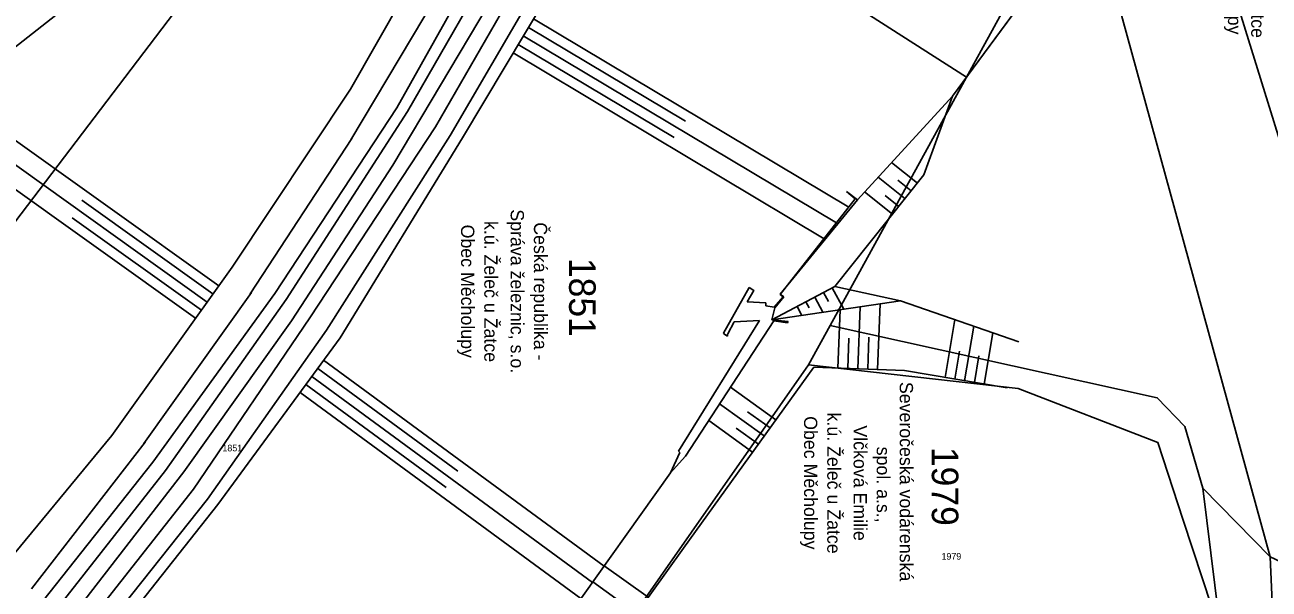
# Model space of a CAD drawing. Extents: x -801372 to -800991, y -1017235 to -1016862.
# Drawn here: x -801166.4 to -801072.7, y -1017121 to -1017078.6 of the extents above; entities that cross this region are included whole.
import ezdxf

# ---------------------------------------------------------------- set-up
doc = ezdxf.new("R2010")
doc.units = 0
for name, color, linetype in [('05a - kolej - svršek', 7, 'Continuous'), ('09 - stávající terén', 7, 'Continuous'), ('19 - katastr', 7, 'Continuous'), ('19b - katastr - hranice SŽDC', 7, 'Continuous'), ('19b - katastr popisy', 7, 'Continuous'), ('21g - SZDC', 7, 'Continuous'), ('26 - obvod_stavby', 7, 'Continuous'), ('27 - dočasné zábory', 7, 'Continuous'), ('Vrstva 1 - kolej', 7, 'Continuous'), ('Vrstva 25', 7, 'Continuous'), ('Vrstva 48 - svahy', 7, 'Continuous')]:
    doc.layers.add(name, color=color, linetype=linetype)

msp = doc.modelspace()

# ---------------------------------------------------------------- linework, layer by layer
for points in [[(-801079.49, -1017062.745), (-801060.39, -1017124.37)], [(-801086.965, -1017066.29), (-801072.61, -1017118.61)]]:
    msp.add_lwpolyline(points)
at = {"layer": '05a - kolej - svršek'}
for p, q in [((-801130.649, -1017070.959), (-801138.418, -1017084.801)), ((-801129.736, -1017071.4), (-801137.615, -1017085.081)), ((-801127.508, -1017072.406), (-801135.493, -1017086.234)), ((-801126.271, -1017073.005), (-801134.396, -1017086.885)), ((-801138.418, -1017084.801), (-801147.606, -1017098.787)), ((-801137.615, -1017085.081), (-801146.745, -1017099.245)), ((-801135.493, -1017086.234), (-801144.954, -1017100.614)), ((-801134.396, -1017086.885), (-801143.698, -1017101.543)), ((-801147.606, -1017098.787), (-801156.793, -1017111.486)), ((-801146.745, -1017099.245), (-801155.831, -1017112.103)), ((-801144.954, -1017100.614), (-801153.731, -1017113.517)), ((-801143.698, -1017101.543), (-801152.664, -1017114.263)), ((-801156.793, -1017111.486), (-801167.183, -1017124.594)), ((-801155.831, -1017112.103), (-801166.305, -1017125.438)), ((-801153.731, -1017113.517), (-801164.481, -1017127.151)), ((-801152.664, -1017114.263), (-801163.522, -1017127.928))]:
    msp.add_line(p, q, dxfattribs=at)
at = {"layer": '09 - stávající terén'}
for p, q in [((-801133.541, -1017068.702), (-801141.901, -1017083.399)), ((-801086.638, -1017070.523), (-801096.55, -1017083.938)), ((-801125.337, -1017073.453), (-801133.459, -1017087.061)), ((-801141.901, -1017083.399), (-801150.824, -1017096.807)), ((-801096.55, -1017083.938), (-801103.705, -1017091.722)), ((-801096.55, -1017083.938), (-801098.707, -1017089.859)), ((-801133.459, -1017087.061), (-801142.687, -1017102.127)), ((-801098.707, -1017089.859), (-801105.414, -1017098.252)), ((-801104.54, -1017091.105), (-801103.863, -1017091.657)), ((-801103.705, -1017091.722), (-801104.54, -1017091.105)), ((-801103.705, -1017091.722), (-801109.519, -1017098.831)), ((-801103.863, -1017091.657), (-801109.513, -1017098.855)), ((-801150.824, -1017096.807), (-801159.87, -1017109.48)), ((-801111.869, -1017098.328), (-801113.784, -1017101.768)), ((-801112.004, -1017099.415), (-801111.497, -1017098.559)), ((-801111.503, -1017098.564), (-801111.869, -1017098.328)), ((-801111.486, -1017098.551), (-801111.503, -1017098.564)), ((-801111.497, -1017098.559), (-801111.486, -1017098.551)), ((-801105.414, -1017098.252), (-801110.142, -1017100.764)), ((-801105.414, -1017098.252), (-801100.47, -1017099.329)), ((-801110.612, -1017099.486), (-801112.004, -1017099.415)), ((-801110.613, -1017099.715), (-801110.612, -1017099.486)), ((-801109.972, -1017099.809), (-801110.613, -1017099.715)), ((-801100.47, -1017099.329), (-801110.142, -1017100.764)), ((-801109.302, -1017099.025), (-801109.972, -1017099.809)), ((-801109.252, -1017099.032), (-801109.917, -1017099.874)), ((-801109.519, -1017098.831), (-801109.252, -1017099.032)), ((-801109.513, -1017098.855), (-801109.302, -1017099.025)), ((-801091.548, -1017102.426), (-801100.47, -1017099.329)), ((-801109.917, -1017099.874), (-801110.142, -1017100.764)), ((-801111.071, -1017100.816), (-801117.181, -1017110.653)), ((-801109.999, -1017100.832), (-801116.67, -1017111.043)), ((-801113.456, -1017101.819), (-801113.001, -1017100.926)), ((-801113.001, -1017100.926), (-801111.071, -1017100.816)), ((-801110.142, -1017100.764), (-801108.913, -1017100.881)), ((-801108.973, -1017100.998), (-801109.999, -1017100.832)), ((-801108.913, -1017100.881), (-801108.973, -1017100.998)), ((-801142.687, -1017102.127), (-801151.894, -1017114.681)), ((-801113.784, -1017101.768), (-801113.776, -1017101.814)), ((-801113.776, -1017101.814), (-801113.503, -1017101.994)), ((-801113.503, -1017101.994), (-801113.499, -1017101.848)), ((-801113.499, -1017101.848), (-801113.456, -1017101.819)), ((-801106.994, -1017104.331), (-801116.808, -1017117.962)), ((-801100.146, -1017104.593), (-801106.994, -1017104.331)), ((-801092.417, -1017105.892), (-801100.146, -1017104.593)), ((-801159.87, -1017109.48), (-801170.36, -1017122.16)), ((-801117.096, -1017110.764), (-801117.791, -1017112.285)), ((-801117.181, -1017110.653), (-801117.096, -1017110.764)), ((-801116.693, -1017111.05), (-801117.791, -1017112.285)), ((-801116.67, -1017111.043), (-801116.693, -1017111.05)), ((-801117.791, -1017112.285), (-801125.65, -1017123.325)), ((-801151.894, -1017114.681), (-801163.062, -1017128.79)), ((-801116.808, -1017117.962), (-801124.431, -1017128.573))]:
    msp.add_line(p, q, dxfattribs=at)
at = {"layer": '19 - katastr'}
for p, q in [((-801105.75, -1017101.2), (-801107.38, -1017104.16)), ((-801076.29, -1017124.55), (-801077.69, -1017113.44))]:
    msp.add_line(p, q, dxfattribs=at)
for points in [[(-801077.69, -1017113.44), (-801079.03, -1017108.8), (-801081.11, -1017106.63), (-801105.75, -1017101.2)], [(-801076.29, -1017124.55), (-801079.17, -1017115.86), (-801081.08, -1017110), (-801091.59, -1017105.94), (-801107.38, -1017104.16)], [(-801077.69, -1017113.44), (-801072.61, -1017118.61), (-801060.39, -1017124.37), (-801036.16, -1017131.43), (-801018.45, -1017131.86), (-801012.13, -1017133.6)]]:
    msp.add_lwpolyline(points, dxfattribs=at)
at = {"layer": '19b - katastr - hranice SŽDC'}
msp.add_line((-801107.38, -1017104.16), (-801120.85, -1017123.38), dxfattribs=at)
for points in [[(-801179.48, -1017100.28), (-801169.74, -1017082.25), (-801157.42, -1017072.56), (-801145.88, -1017061.68), (-801137.41, -1017046.38), (-801149.55, -1017039.8), (-801149.01, -1017037.86)], [(-801085.03, -1017062.08), (-801088.9, -1017070.5), (-801105.75, -1017101.2)]]:
    msp.add_lwpolyline(points, dxfattribs=at)
at = {"layer": '21g - SZDC'}
for p, q in [((-801134.701, -1017075.184), (-801141.881, -1017087.226)), ((-801141.8, -1017087.101), (-801149.445, -1017098.82)), ((-801149.359, -1017098.699), (-801157.458, -1017110.089)), ((-801157.364, -1017109.969), (-801165.934, -1017121.022))]:
    msp.add_line(p, q, dxfattribs=at)
at = {"layer": '26 - obvod_stavby'}
msp.add_lwpolyline([(-801085.002, -1017062.083), (-801079.49, -1017062.745), (-801060.39, -1017124.37), (-801060.39, -1017137.347), (-801071.855, -1017135.755), (-801072.61, -1017118.61), (-801086.965, -1017066.29), (-801086.638, -1017070.523), (-801095.483, -1017082.494), (-801141.216, -1017053.254), (-801148.66, -1017042.443), (-801151.48, -1017039.58)], dxfattribs=at)
at = {"layer": '27 - dočasné zábory'}
msp.add_lwpolyline([(-801072.61, -1017118.61), (-801086.965, -1017066.29), (-801085.03, -1017062.08), (-801079.49, -1017062.745), (-801060.39, -1017124.37), (-801072.61, -1017118.61)], dxfattribs=at)
at = {"layer": 'Vrstva 1 - kolej'}
for p, q in [((-801131.529, -1017077.075), (-801138.709, -1017089.117)), ((-801138.709, -1017089.117), (-801146.354, -1017100.836)), ((-801146.354, -1017100.836), (-801154.453, -1017112.226)), ((-801154.453, -1017112.226), (-801163.023, -1017123.279))]:
    msp.add_line(p, q, dxfattribs=at)
at = {"layer": 'Vrstva 25'}
msp.add_line((-801174.849, -1017103.46), (-801151.855, -1017073.26), dxfattribs=at)
at = {"layer": 'Vrstva 48 - svahy'}
for p, q in [((-801128.11, -1017078.099), (-801104.352, -1017092.279)), ((-801128.494, -1017078.743), (-801116.656, -1017085.809)), ((-801129.263, -1017080.031), (-801117.508, -1017087.047)), ((-801128.879, -1017079.387), (-801105.285, -1017093.469)), ((-801129.648, -1017080.675), (-801106.219, -1017094.659)), ((-801151.822, -1017098.205), (-801171.819, -1017083.931)), ((-801152.693, -1017099.426), (-801172.26, -1017085.459)), ((-801153.565, -1017100.647), (-801172.978, -1017086.789)), ((-801099.191, -1017090.465), (-801101.127, -1017088.918)), ((-801100.127, -1017091.637), (-801102.145, -1017090.025)), ((-801099.659, -1017091.051), (-801100.648, -1017090.261)), ((-801101.064, -1017092.808), (-801103.162, -1017091.131)), ((-801152.257, -1017098.815), (-801162.134, -1017091.765)), ((-801100.596, -1017092.222), (-801101.625, -1017091.4)), ((-801153.129, -1017100.036), (-801162.874, -1017093.08)), ((-801106.26, -1017098.701), (-801105.894, -1017099.39)), ((-801105.598, -1017098.35), (-801104.741, -1017099.963)), ((-801107.585, -1017099.405), (-801107.344, -1017099.859)), ((-801106.922, -1017099.053), (-801106.315, -1017100.196)), ((-801102.183, -1017104.515), (-801101.993, -1017099.555)), ((-801108.247, -1017099.757), (-801107.89, -1017100.43)), ((-801105.181, -1017104.4), (-801105.013, -1017100.003)), ((-801103.682, -1017104.458), (-801103.503, -1017099.779)), ((-801097.104, -1017105.104), (-801096.373, -1017100.751)), ((-801095.625, -1017105.353), (-801094.935, -1017101.25)), ((-801104.431, -1017104.429), (-801104.345, -1017102.16)), ((-801102.933, -1017104.486), (-801102.84, -1017102.077)), ((-801094.146, -1017105.601), (-801093.498, -1017101.749)), ((-801096.365, -1017105.229), (-801096.009, -1017103.115)), ((-801143.926, -1017103.817), (-801122.795, -1017119.315)), ((-801094.885, -1017105.477), (-801094.551, -1017103.488)), ((-801144.813, -1017105.027), (-801123.665, -1017120.537)), ((-801144.37, -1017104.422), (-801133.8, -1017112.174)), ((-801145.701, -1017106.236), (-801124.535, -1017121.759)), ((-801145.257, -1017105.631), (-801134.679, -1017113.39)), ((-801109.849, -1017108.297), (-801113.268, -1017105.835)), ((-801110.726, -1017109.514), (-801114.089, -1017107.092)), ((-801110.287, -1017108.905), (-801111.983, -1017107.685)), ((-801111.602, -1017110.731), (-801114.91, -1017108.349)), ((-801111.164, -1017110.123), (-801112.832, -1017108.922)), ((-801119.467, -1017121.664), (-801122.776, -1017119.287)), ((-801120.343, -1017122.882), (-801123.646, -1017120.509))]:
    msp.add_line(p, q, dxfattribs=at)

# ---------------------------------------------------------------- texts
at = {"layer": '19b - katastr popisy'}
for s, height, p in [('Obec Měcholupy', 1.00005, (-801075.786, -1017069.245)), ('k.ú. Želeč u Žatce ', 1.00005, (-801074.035, -1017068.915)), ('Správa železnic, s.o.', 1.00005, (-801129.831, -1017092.448)), ('Obec Měcholupy', 1.00005, (-801133.568, -1017093.599)), ('k.ú. Želeč u Žatce ', 1.00005, (-801131.817, -1017093.325)), ('Česká republika - ', 1.00005, (-801128.08, -1017093.422)), ('1851', 2, (-801125.427, -1017096.102)), ('Severočeská vodárenská ', 1.00005, (-801100.518, -1017105.443)), ('Obec Měcholupy', 1.00005, (-801107.728, -1017108.025)), ('k.ú. Želeč u Žatce ', 1.00005, (-801105.977, -1017107.75)), ('Vlčková Emilie', 1.00005, (-801103.991, -1017108.716)), ('spol. a.s.,', 1.00005, (-801102.251, -1017110.32)), ('1979', 2, (-801098.1, -1017110.332))]:
    msp.add_text(s, height=height, rotation=270, dxfattribs=at).set_placement(p)
for s, p in [('1851', (-801151.546, -1017110.673)), ('1979', (-801097.37, -1017118.83))]:
    msp.add_text(s, height=0.5, dxfattribs=at).set_placement(p)

doc.saveas('drawing.dxf')
